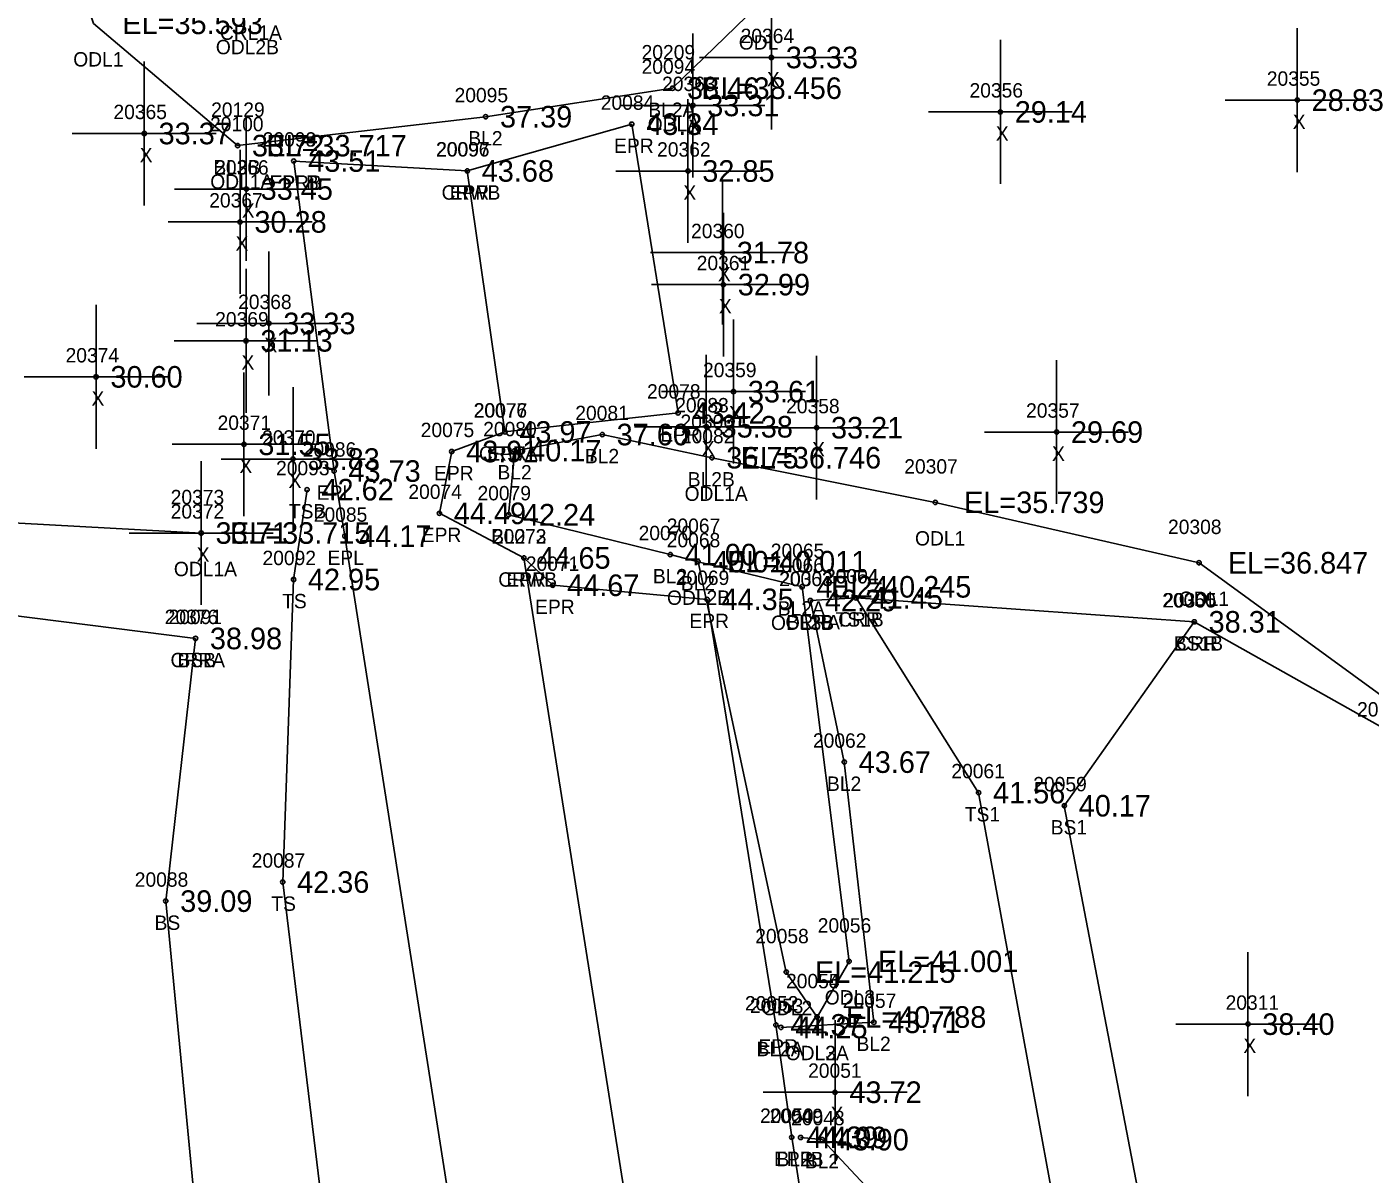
# Model space of a CAD drawing. Extents: x 2619569 to 2620117, y 784503 to 785150.
# Drawn here: x 2619804.3 to 2619897.7, y 784762.6 to 784842.3 of the extents above; entities that cross this region are included whole.
import ezdxf

# ---------------------------------------------------------------- set-up
doc = ezdxf.new("R2010")
doc.units = 0
for name, color, linetype in [('RD_DTM_BkLn1', 7, 'Continuous'), ('RD_DTM_BkLn2', 7, 'Continuous'), ('RD_DTM_BkLn_txCode', 7, 'Continuous'), ('RD_EX_H2O', 7, 'Continuous'), ('RD_EX_H2O_txCode', 7, 'Continuous'), ('RD_EX_Misc', 7, 'Continuous'), ('RD_EX_Misc_txCode', 7, 'Continuous'), ('RD_EX_Road', 7, 'Continuous'), ('RD_EX_Road_txCode', 7, 'Continuous'), ('RD_EX_TX_H2O_ELEV', 7, 'Continuous'), ('RD_EX_TX_Misc_ELEV', 7, 'Continuous'), ('RD_EX_TX_Road_ELEV', 7, 'Continuous'), ('RD_HC_Survey_ELEV', 7, 'Continuous'), ('RD_HC_Survey_txCode', 7, 'Continuous'), ('RD_SMD_Locator', 7, 'Continuous')]:
    doc.layers.add(name, color=color, linetype=linetype)

msp = doc.modelspace()

# ---------------------------------------------------------------- linework, layer by layer
at = {"layer": 'RD_DTM_BkLn1'}
msp.add_line((2619837.558, 784814.155), (2619834.944, 784832.302), dxfattribs=at)
for points in [[(2619849.213, 784838.053), (2619836.215, 784836.069), (2619818.975, 784834.059)], [(2619858.211, 784803.39), (2619850.984, 784805.136), (2619849.045, 784805.629), (2619837.808, 784808.4), (2619838.244, 784812.854), (2619844.32, 784813.975), (2619851.942, 784812.364)], [(2619883.081, 784523.277), (2619865.989, 784633.651), (2619850.158, 784734.2), (2619838.88, 784805.398)], [(2619856.739, 784772.759), (2619863.196, 784773.118), (2619861.144, 784791.204), (2619858.791, 784802.438)], [(2619868.663, 784700.776), (2619870.558, 784704.133), (2619873.228, 784718.403), (2619870.267, 784738.763), (2619867.258, 784756.786), (2619859.604, 784764.961), (2619858.107, 784765.108)]]:
    msp.add_lwpolyline(points, dxfattribs=at)
at = {"layer": 'RD_DTM_BkLn2'}
for points in [[(2619856.045, 784520.482), (2619839.862, 784632.849), (2619828.246, 784732.472), (2619822.116, 784782.865), (2619822.867, 784803.897), (2619823.809, 784810.143)], [(2619902.706, 784523.566), (2619889.374, 784638.026), (2619879.627, 784739.193), (2619870.479, 784789.078), (2619861.967, 784802.623)], [(2619955.536, 784515.686), (2619919.199, 784522.052), (2619897.305, 784638.514), (2619886.404, 784736.094), (2619876.434, 784788.173), (2619885.461, 784800.956)], [(2619851.2, 784519.249), (2619834.864, 784632.711), (2619818.816, 784731.213), (2619813.988, 784781.541), (2619816.054, 784799.8)]]:
    msp.add_lwpolyline(points, dxfattribs=at)
at = {"layer": 'RD_EX_H2O'}
for points in [[(2619818.975, 784834.059), (2619808.965, 784842.559), (2619802.242, 784862.109), (2619788.776, 784932.49), (2619768.719, 785027.955), (2619758.968, 785087.806)], [(2619849.213, 784838.053), (2619855.055, 784843.735), (2619862.979, 784854.681), (2619876.772, 784858.944), (2619905.894, 784860.527), (2619923.246, 784863.85), (2619948.053, 784872.759), (2619969.079, 784848.673), (2619985.638, 784830.75), (2619975.853, 784807.963), (2619978.047, 784802.932), (2620013.477, 784773.679)], [(2619816.447, 784807.129), (2619791.12, 784808.519), (2619763.979, 784833.058), (2619735.515, 784849.523), (2619695.729, 784853.407), (2619649.584, 784841.565), (2619599.667, 784837.827)], [(2619816.054, 784799.8), (2619788.012, 784803.334), (2619762.859, 784832.157), (2619731.326, 784842.738), (2619695.494, 784847.411), (2619650.289, 784835.607), (2619600.265, 784824.841)], [(2619851.942, 784812.364), (2619867.467, 784809.26), (2619885.797, 784805.059), (2619903.554, 784792.135), (2619903.391, 784761.344), (2619912.697, 784719.269), (2619932.068, 784700.307), (2619950.07, 784661.695), (2619964.862, 784626.79)], [(2619859.25, 784773.483), (2619857.111, 784776.609), (2619850.984, 784805.136)], [(2619859.25, 784773.483), (2619861.477, 784777.354), (2619858.211, 784803.39)], [(2619858.791, 784802.438), (2619861.967, 784802.623), (2619885.461, 784800.956), (2619898.935, 784793.372), (2619901.362, 784760.214), (2619910.658, 784718.327), (2619929.658, 784699.527), (2619944.471, 784658.003), (2619963.477, 784625.348)]]:
    msp.add_lwpolyline(points, dxfattribs=at)
at = {"layer": 'RD_EX_Misc'}
for p, q in [((2619856.078, 784835.186), (2619856.078, 784845.186)), ((2619892.623, 784832.222), (2619892.623, 784842.222)), ((2619850.62, 784831.853), (2619850.62, 784841.853)), ((2619871.987, 784831.402), (2619871.987, 784841.402)), ((2619812.49, 784829.903), (2619812.49, 784839.903)), ((2619851.078, 784840.186), (2619861.078, 784840.186)), ((2619845.62, 784836.853), (2619855.62, 784836.853)), ((2619850.274, 784827.294), (2619850.274, 784837.294)), ((2619887.623, 784837.222), (2619897.623, 784837.222)), ((2619819.584, 784826.042), (2619819.584, 784836.042)), ((2619866.987, 784836.402), (2619876.987, 784836.402)), ((2619807.49, 784834.903), (2619817.49, 784834.903)), ((2619819.15, 784823.758), (2619819.15, 784833.758)), ((2619845.274, 784832.294), (2619855.274, 784832.294)), ((2619814.584, 784831.042), (2619824.584, 784831.042)), ((2619852.674, 784821.626), (2619852.674, 784831.626)), ((2619852.742, 784819.398), (2619852.742, 784829.398)), ((2619814.15, 784828.758), (2619824.15, 784828.758)), ((2619821.156, 784816.698), (2619821.156, 784826.698)), ((2619847.674, 784826.626), (2619857.674, 784826.626)), ((2619819.563, 784815.49), (2619819.563, 784825.49)), ((2619847.742, 784824.398), (2619857.742, 784824.398)), ((2619809.141, 784812.986), (2619809.141, 784822.986)), ((2619816.156, 784821.698), (2619826.156, 784821.698)), ((2619853.441, 784811.961), (2619853.441, 784821.961)), ((2619814.563, 784820.49), (2619824.563, 784820.49)), ((2619851.551, 784809.515), (2619851.551, 784819.515)), ((2619859.219, 784809.452), (2619859.219, 784819.452)), ((2619875.894, 784809.147), (2619875.894, 784819.147)), ((2619804.141, 784817.986), (2619814.141, 784817.986)), ((2619819.421, 784808.297), (2619819.421, 784818.297)), ((2619822.838, 784807.27), (2619822.838, 784817.27)), ((2619848.441, 784816.961), (2619858.441, 784816.961)), ((2619846.551, 784814.515), (2619856.551, 784814.515)), ((2619854.219, 784814.452), (2619864.219, 784814.452)), ((2619870.894, 784814.147), (2619880.894, 784814.147)), ((2619814.421, 784813.297), (2619824.421, 784813.297)), ((2619817.838, 784812.27), (2619827.838, 784812.27)), ((2619816.447, 784802.129), (2619816.447, 784812.129)), ((2619811.447, 784807.129), (2619821.447, 784807.129)), ((2619889.193, 784767.989), (2619889.193, 784777.989)), ((2619860.502, 784763.258), (2619860.502, 784773.258)), ((2619884.193, 784772.989), (2619894.193, 784772.989)), ((2619855.502, 784768.258), (2619865.502, 784768.258))]:
    msp.add_line(p, q, dxfattribs=at)
at = {"layer": 'RD_EX_Road'}
for points in [[(2619895.757, 784524.852), (2619878.518, 784636.421), (2619867.915, 784700.675), (2619864.839, 784718.105), (2619862.044, 784735.866), (2619857.486, 784765.125), (2619856.395, 784772.937), (2619851.609, 784802.518), (2619840.882, 784803.499), (2619838.88, 784805.398), (2619833.006, 784808.498), (2619833.861, 784812.796), (2619837.558, 784814.155), (2619849.591, 784815.474), (2619846.374, 784835.551), (2619834.944, 784832.302), (2619822.882, 784832.99)], [(2619871.291, 784521.473), (2619854.199, 784633.244), (2619837.85, 784734.181), (2619826.432, 784806.913), (2619825.685, 784811.438), (2619822.882, 784832.99)]]:
    msp.add_lwpolyline(points, dxfattribs=at)
at = {"layer": 'RD_SMD_Locator'}
for centre in [(2619856.078, 784840.186), (2619849.213, 784838.053), (2619849.213, 784838.053), (2619850.62, 784836.853), (2619871.987, 784836.402), (2619892.623, 784837.222), (2619836.215, 784836.069), (2619846.374, 784835.551), (2619812.49, 784834.903), (2619818.975, 784834.059), (2619818.975, 784834.059), (2619822.882, 784832.99), (2619822.882, 784832.99), (2619834.944, 784832.302), (2619834.944, 784832.302), (2619850.274, 784832.294), (2619819.584, 784831.042), (2619819.15, 784828.758), (2619852.674, 784826.626), (2619852.742, 784824.398), (2619821.156, 784821.698), (2619819.563, 784820.49), (2619809.141, 784817.986), (2619853.441, 784816.961), (2619849.591, 784815.474), (2619837.558, 784814.155), (2619837.558, 784814.155), (2619844.32, 784813.975), (2619851.551, 784814.515), (2619859.219, 784814.452), (2619875.894, 784814.147), (2619819.421, 784813.297), (2619822.838, 784812.27), (2619833.861, 784812.796), (2619838.244, 784812.854), (2619851.942, 784812.364), (2619851.942, 784812.364), (2619825.685, 784811.438), (2619823.809, 784810.143), (2619867.467, 784809.26), (2619833.006, 784808.498), (2619837.808, 784808.4), (2619816.447, 784807.129), (2619816.447, 784807.129), (2619826.432, 784806.913), (2619849.045, 784805.629), (2619838.88, 784805.398), (2619838.88, 784805.398), (2619850.984, 784805.136), (2619850.984, 784805.136), (2619885.797, 784805.059), (2619822.867, 784803.897), (2619840.882, 784803.499), (2619858.211, 784803.39), (2619858.211, 784803.39), (2619851.609, 784802.518), (2619858.791, 784802.438), (2619858.791, 784802.438), (2619861.967, 784802.623), (2619861.967, 784802.623), (2619885.461, 784800.956), (2619885.461, 784800.956), (2619816.054, 784799.8), (2619816.054, 784799.8), (2619861.144, 784791.204), (2619870.479, 784789.078), (2619876.434, 784788.173), (2619822.116, 784782.865), (2619813.988, 784781.541), (2619857.111, 784776.609), (2619861.477, 784777.354), (2619856.395, 784772.937), (2619859.25, 784773.483), (2619859.25, 784773.483), (2619863.196, 784773.118), (2619889.193, 784772.989), (2619856.739, 784772.759), (2619860.502, 784768.258), (2619857.486, 784765.125), (2619858.107, 784765.108), (2619859.604, 784764.961)]:
    msp.add_circle(centre, 0.15, dxfattribs=at)

# ---------------------------------------------------------------- texts
at = {"layer": 'RD_DTM_BkLn_txCode'}
for s, p in [('20094', (2619847.055, 784839.053)), ('20095', (2619834.058, 784837.069)), ('BL2A', (2619847.52, 784836.053)), ('20100', (2619817.062, 784835.059)), ('BL2', (2619835.011, 784834.069)), ('BL2B', (2619817.298, 784832.059)), ('20081', (2619842.446, 784814.975)), ('20080', (2619836.047, 784813.854)), ('20082', (2619849.784, 784813.364)), ('BL2', (2619843.115, 784811.975)), ('20093', (2619821.652, 784811.143)), ('BL2', (2619837.039, 784810.854)), ('BL2B', (2619850.264, 784810.364)), ('20079', (2619835.65, 784809.4)), ('TSB', (2619822.542, 784808.143)), ('20070', (2619846.848, 784806.629)), ('BL2', (2619836.603, 784806.4)), ('20068', (2619848.803, 784806.136)), ('20092', (2619820.71, 784804.897)), ('20066', (2619856.007, 784804.39)), ('BL2', (2619847.84, 784803.629)), ('BL2', (2619849.78, 784803.136)), ('20063', (2619856.61, 784803.438)), ('20064', (2619859.786, 784803.623)), ('TS', (2619822.072, 784801.897)), ('20060', (2619883.241, 784801.956)), ('BL2A', (2619856.518, 784801.39)), ('20091', (2619814.18, 784800.8)), ('BL2B', (2619857.114, 784800.438)), ('TS1B', (2619860.534, 784800.623)), ('BS1B', (2619884.044, 784798.956)), ('BSB', (2619814.802, 784797.8)), ('20062', (2619858.962, 784792.204)), ('20061', (2619868.581, 784790.078)), ('BL2', (2619859.939, 784789.204)), ('20059', (2619874.276, 784789.173)), ('TS1', (2619869.518, 784787.078)), ('BS1', (2619875.489, 784786.173)), ('20087', (2619819.958, 784783.865)), ('20088', (2619811.831, 784782.541)), ('TS', (2619821.32, 784780.865)), ('BS', (2619813.209, 784779.541)), ('20057', (2619861.039, 784774.118)), ('20053', (2619854.582, 784773.759)), ('BL2', (2619861.991, 784771.118)), ('BL2A', (2619855.046, 784770.759)), ('20049', (2619855.949, 784766.108)), ('20048', (2619857.447, 784765.961)), ('BL2B', (2619856.429, 784763.108)), ('BL2', (2619858.4, 784762.961))]:
    msp.add_text(s, height=1, dxfattribs=at).set_placement(p)
at = {"layer": 'RD_EX_H2O_txCode'}
for s, p in [('CRL1A', (2619817.751, 784841.412)), ('ODL2B', (2619817.467, 784840.412)), ('ODL', (2619853.811, 784840.735)), ('ODL1', (2619807.556, 784839.559)), ('20209', (2619847.055, 784840.053)), ('20129', (2619817.141, 784836.059)), ('ODLA', (2619847.48, 784835.053)), ('ODL1A', (2619817.078, 784831.059)), ('20306', (2619849.76, 784814.364)), ('20307', (2619865.31, 784811.26)), ('ODL1A', (2619850.044, 784809.364)), ('20373', (2619814.328, 784809.129)), ('20067', (2619848.803, 784807.136)), ('20308', (2619883.64, 784807.059)), ('ODL1', (2619866.058, 784806.26)), ('20065', (2619856.03, 784805.39)), ('ODL1A', (2619814.549, 784804.129)), ('20303', (2619856.633, 784803.438)), ('20304', (2619859.81, 784803.623)), ('ODL2B', (2619848.819, 784802.136)), ('20305', (2619883.304, 784801.956)), ('ODL1', (2619884.388, 784802.059)), ('20376', (2619813.912, 784800.8)), ('ODL3B', (2619856.046, 784800.39)), ('CRRA', (2619857.051, 784800.438)), ('CRR', (2619860.715, 784800.623)), ('CRR', (2619884.209, 784798.956)), ('CRRA', (2619814.314, 784797.8)), ('20309', (2619896.777, 784794.372)), ('20058', (2619854.954, 784778.609)), ('20056', (2619859.295, 784779.354)), ('20054', (2619857.092, 784775.483)), ('20055', (2619857.092, 784775.483)), ('ODL3', (2619859.784, 784774.354)), ('ODL2', (2619855.418, 784773.609)), ('ODL2A', (2619857.068, 784770.483)), ('ODL3A', (2619857.068, 784770.483))]:
    msp.add_text(s, height=1, dxfattribs=at).set_placement(p)
at = {"layer": 'RD_EX_Misc_txCode'}
for s, p in [('20364', (2619853.937, 784841.186)), ('20363', (2619848.478, 784837.853)), ('X', (2619855.763, 784838.186)), ('20356', (2619869.845, 784837.402)), ('20355', (2619890.505, 784838.222)), ('20365', (2619810.348, 784835.903)), ('X', (2619850.305, 784834.853)), ('X', (2619892.308, 784835.222)), ('X', (2619871.672, 784834.402)), ('X', (2619812.175, 784832.903)), ('20362', (2619848.132, 784833.294)), ('20366', (2619817.419, 784832.042)), ('X', (2619849.959, 784830.294)), ('20367', (2619817.008, 784829.758)), ('X', (2619819.269, 784829.042)), ('20360', (2619850.493, 784827.626)), ('X', (2619818.835, 784826.758)), ('20361', (2619850.884, 784825.398)), ('X', (2619852.359, 784824.626)), ('20368', (2619819.014, 784822.698)), ('20369', (2619817.421, 784821.49)), ('X', (2619852.427, 784822.398)), ('X', (2619820.841, 784819.698)), ('20374', (2619807.023, 784818.986)), ('X', (2619819.248, 784818.49)), ('20359', (2619851.323, 784817.961)), ('X', (2619808.826, 784815.986)), ('20083', (2619849.394, 784815.515)), ('X', (2619853.126, 784814.961)), ('20358', (2619857.101, 784815.452)), ('20357', (2619873.776, 784815.147)), ('20371', (2619817.587, 784814.297)), ('20370', (2619820.68, 784813.27)), ('X', (2619851.236, 784812.515)), ('X', (2619858.904, 784812.452)), ('X', (2619875.579, 784812.147)), ('X', (2619819.106, 784811.297)), ('X', (2619822.523, 784810.27)), ('20372', (2619814.328, 784808.129)), ('X', (2619816.132, 784805.129)), ('20311', (2619887.642, 784773.989)), ('X', (2619888.878, 784770.989)), ('20051', (2619858.628, 784769.258)), ('X', (2619860.187, 784766.258))]:
    msp.add_text(s, height=1, dxfattribs=at).set_placement(p)
at = {"layer": 'RD_EX_Road_txCode'}
for s, p in [('20084', (2619844.216, 784836.551)), ('20098', (2619820.725, 784833.99)), ('20099', (2619820.725, 784833.99)), ('20096', (2619832.762, 784833.302)), ('EPR', (2619845.145, 784833.551)), ('EPRB', (2619821.181, 784830.99)), ('EPLB', (2619821.205, 784830.99)), ('EPR', (2619833.715, 784830.302)), ('20078', (2619847.433, 784816.474)), ('20076', (2619835.376, 784815.155)), ('20075', (2619831.704, 784813.796)), ('EPR', (2619848.362, 784813.474)), ('20086', (2619823.504, 784812.438)), ('EPR', (2619836.329, 784812.155)), ('EPR', (2619832.633, 784810.796)), ('EPL', (2619824.481, 784809.438)), ('20074', (2619830.848, 784809.498)), ('20085', (2619824.274, 784807.913)), ('EPR', (2619831.778, 784806.498)), ('20072', (2619836.722, 784806.398)), ('EPL', (2619825.227, 784804.913)), ('20071', (2619839.008, 784804.499)), ('EPR', (2619837.652, 784803.398)), ('20069', (2619849.428, 784803.518)), ('EPR', (2619839.654, 784801.499)), ('EPR', (2619850.381, 784800.518)), ('20052', (2619854.237, 784773.937)), ('EPR', (2619855.166, 784770.937)), ('20050', (2619855.29, 784766.125)), ('EPR', (2619856.258, 784763.125))]:
    msp.add_text(s, height=1, dxfattribs=at).set_placement(p)
at = {"layer": 'RD_EX_TX_H2O_ELEV'}
for s, p in [('EL=35.593', (2619810.965, 784841.809)), ('EL=38.456', (2619851.213, 784837.303)), ('EL=33.717', (2619820.975, 784833.309)), ('EL=36.746', (2619853.942, 784811.614)), ('EL=35.739', (2619869.467, 784808.51)), ('EL=33.715', (2619818.447, 784806.379)), ('EL=40.011', (2619852.984, 784804.386)), ('EL=36.847', (2619887.797, 784804.309)), ('EL=40.245', (2619860.211, 784802.64)), ('42.29', (2619859.791, 784801.688)), ('41.45', (2619862.967, 784801.873)), ('38.31', (2619886.461, 784800.206)), ('38.98', (2619817.054, 784799.05)), ('EL=41.001', (2619863.477, 784776.604)), ('EL=41.215', (2619859.111, 784775.859)), ('EL=40.788', (2619861.25, 784772.733)), ('EL=40.788', (2619861.25, 784772.733))]:
    msp.add_text(s, height=1.5, dxfattribs=at).set_placement(p)
at = {"layer": 'RD_EX_TX_Misc_ELEV'}
for s, p in [('33.33', (2619857.078, 784839.436)), ('38.46', (2619850.213, 784837.303)), ('33.31', (2619851.62, 784836.103)), ('28.83', (2619893.623, 784836.472)), ('37.39', (2619837.215, 784835.319)), ('29.14', (2619872.987, 784835.652)), ('33.37', (2619813.49, 784834.153)), ('33.72', (2619819.975, 784833.309)), ('32.85', (2619851.274, 784831.544)), ('33.45', (2619820.584, 784830.292)), ('30.28', (2619820.15, 784828.008)), ('31.78', (2619853.674, 784825.876)), ('32.99', (2619853.742, 784823.648)), ('33.33', (2619822.156, 784820.948)), ('31.13', (2619820.563, 784819.74)), ('30.60', (2619810.141, 784817.236)), ('33.61', (2619854.441, 784816.211)), ('35.38', (2619852.551, 784813.765)), ('33.21', (2619860.219, 784813.702)), ('31.55', (2619820.421, 784812.547)), ('37.60', (2619845.32, 784813.225)), ('29.69', (2619876.894, 784813.397)), ('40.17', (2619839.244, 784812.104)), ('36.75', (2619852.942, 784811.614)), ('33.83', (2619823.838, 784811.52)), ('42.62', (2619824.809, 784809.393)), ('42.24', (2619838.808, 784807.65)), ('33.71', (2619817.447, 784806.379)), ('41.00', (2619850.045, 784804.879)), ('40.01', (2619851.984, 784804.386)), ('42.95', (2619823.867, 784803.147)), ('40.24', (2619859.211, 784802.64)), ('42.29', (2619859.791, 784801.688)), ('41.45', (2619862.967, 784801.873)), ('38.31', (2619886.461, 784800.206)), ('38.98', (2619817.054, 784799.05)), ('43.67', (2619862.144, 784790.454)), ('41.56', (2619871.479, 784788.328)), ('40.17', (2619877.434, 784787.423)), ('42.36', (2619823.116, 784782.115)), ('39.09', (2619814.988, 784780.791)), ('44.25', (2619857.739, 784772.009)), ('43.71', (2619864.196, 784772.368)), ('38.40', (2619890.193, 784772.239)), ('43.72', (2619861.502, 784767.508)), ('44.09', (2619859.107, 784764.358)), ('43.90', (2619860.604, 784764.211))]:
    msp.add_text(s, height=1.5, dxfattribs=at).set_placement(p)
at = {"layer": 'RD_EX_TX_Road_ELEV'}
for s, p in [('43.34', (2619847.374, 784834.801)), ('43.51', (2619823.882, 784832.24)), ('43.51', (2619823.882, 784832.24)), ('43.68', (2619835.944, 784831.552)), ('43.42', (2619850.591, 784814.724)), ('43.97', (2619838.558, 784813.405)), ('43.91', (2619834.861, 784812.046)), ('43.73', (2619826.685, 784810.688)), ('44.49', (2619834.006, 784807.748)), ('44.17', (2619827.432, 784806.163)), ('44.65', (2619839.88, 784804.648)), ('44.67', (2619841.882, 784802.749)), ('44.35', (2619852.609, 784801.768)), ('44.37', (2619857.395, 784772.187)), ('44.39', (2619858.486, 784764.375))]:
    msp.add_text(s, height=1.5, dxfattribs=at).set_placement(p)
at = {"layer": 'RD_HC_Survey_ELEV'}
for s, p in [('43.68', (2619835.944, 784831.552)), ('43.97', (2619838.558, 784813.405)), ('44.65', (2619839.88, 784804.648))]:
    msp.add_text(s, height=1.5, dxfattribs=at).set_placement(p)
at = {"layer": 'RD_HC_Survey_txCode'}
for s, p in [('20097', (2619832.786, 784833.302)), ('CRWB', (2619833.156, 784830.302)), ('20077', (2619835.4, 784815.155)), ('CRWA', (2619835.754, 784812.155)), ('20073', (2619836.722, 784806.398)), ('CRWB', (2619837.092, 784803.398))]:
    msp.add_text(s, height=1, dxfattribs=at).set_placement(p)

doc.saveas('drawing.dxf')
